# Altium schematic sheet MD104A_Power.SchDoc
size Letter; Date: Not shown in title block; ApprovedBy: Not shown in title block; CheckedBy: Not shown in title block; Author: Not shown in title block; CompanyName: Not shown in title block; Engineer: Not shown in title block; Organization: Not shown in title block; Address1: Not shown in title block; Address2: Not shown in title block; Address3: Not shown in title block; Address4: Not shown in title block; DocumentNumber: 4; Revision: Use project parameter SCH_Rev; SheetNumber: 4; SheetTotal: 5; PageSetup: Record=PageOptions¦CenterHorizontal=True¦CenterVertical=True¦PrintScale=1.00¦XCorrection=1.00¦YCorrection=1.00¦PrintKind=0¦BorderSize=5000000¦LeftOffset=0¦BottomOffset=0¦Orientation=2¦PaperLength=1000¦PaperWidth=1000¦Scale=100¦PaperSource=15¦PrintQuality=600¦MediaType=1¦DitherType=10¦PaperKind=Letter¦PrintScaleMode=1
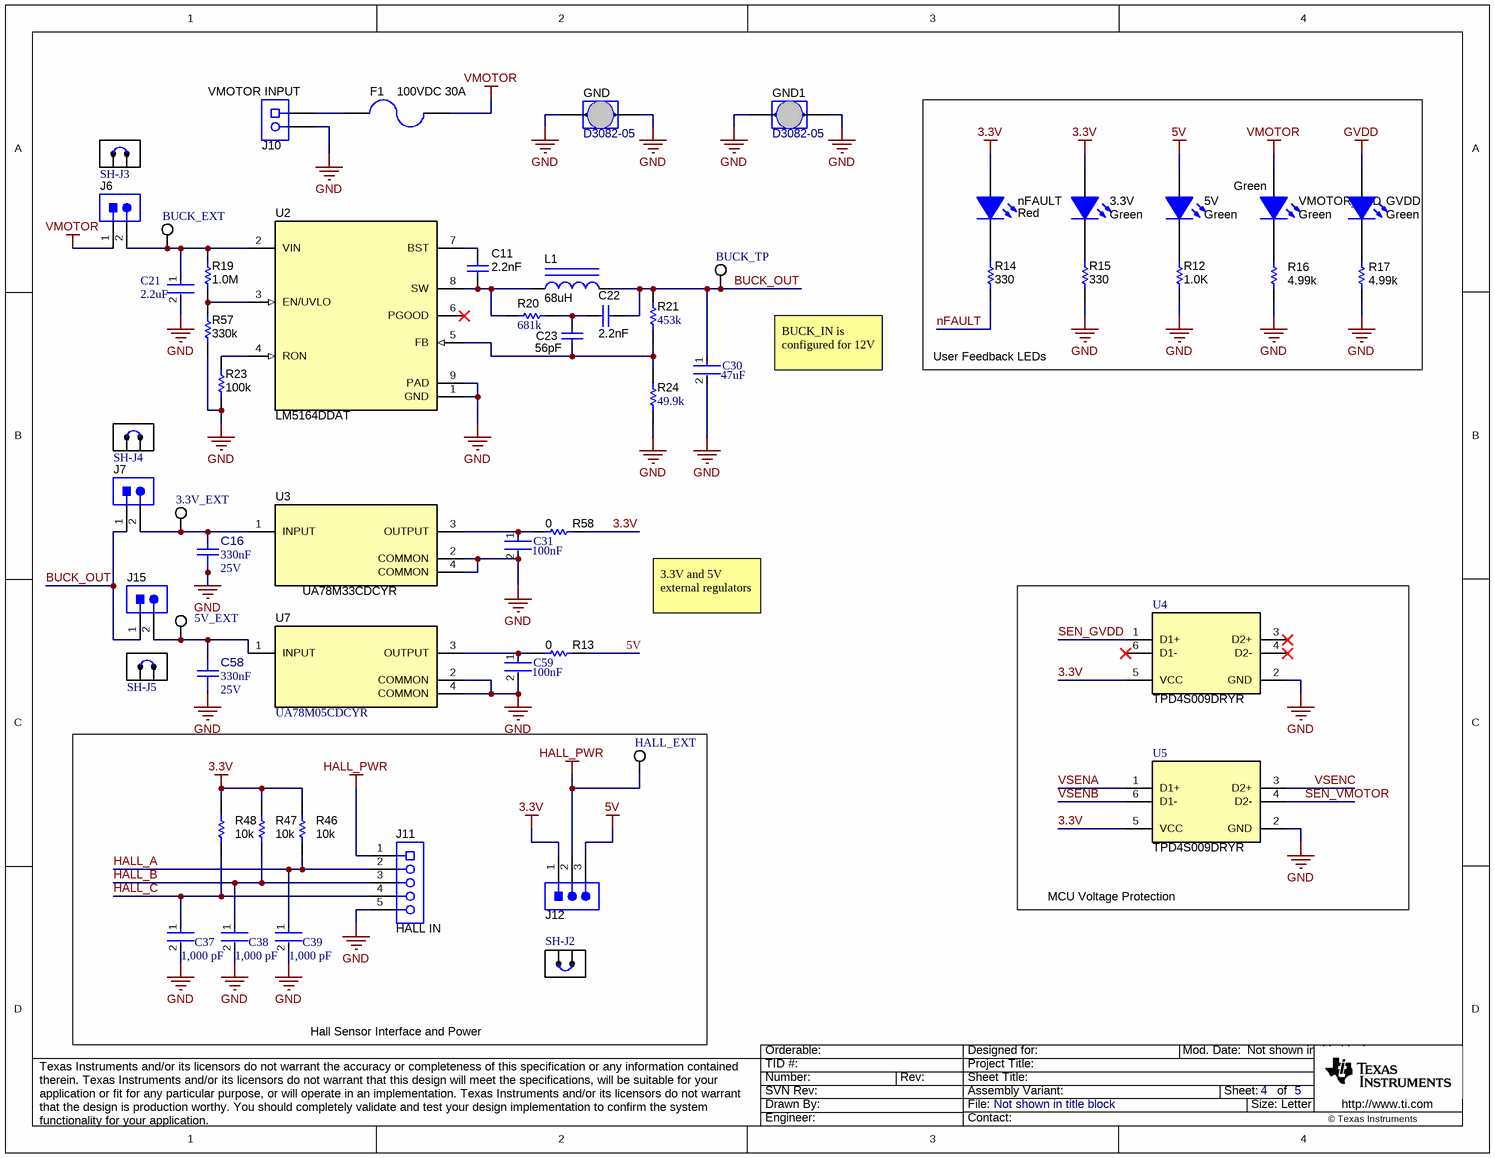
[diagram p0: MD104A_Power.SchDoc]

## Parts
3.3V  value Green  [LED_LTST-C171]
3.3V_EXT  5015  [Testpoint_Keystone_Miniature]  (value not drawn)
5V  5V: Green  [LED_LTST-C171]
5V_EXT  5015  [Testpoint_Keystone_Miniature]  (value not drawn)
BUCK_EXT  5015  [Testpoint_Keystone_Miniature]  (value not drawn)
BUCK_TP  5015  [Testpoint_Keystone_Miniature]  (value not drawn)
C11  Cap_F: 2.2nF  [0603L]  (hidden comment: CGA3E2X7R2A222K080AA)
C16  Cap_F: 330nF  VDC_V: 25V  [FP-CGA3E3X7R1E334K080AB_0603-MFG]  (hidden comment: CGA3E3X7R1E334K080AB)
C21  Capacitance: 2.2uF  [FP-C1210C225K1RACAUTO-MFG]  (hidden comment: C1210C225K1RACAUTO)
C22  Cap_F: 2.2nF  [0603L]  (hidden comment: CGA3E2X7R2A222K080AA)
C23  ValueDisplayed: 56pF  [0603L]  (hidden comment: C0603C560J1RACAUTO)
C30  Capacitance: 47uF  [FP-CGA9P-IPC_A]  (hidden comment: CGA9N3X7R1E476M230KB)
C31  Capacitance: 100nF  [FP-GCM155-0_05-IPC_A]  (hidden comment: GCM155R71C104KA55J)
C37  value 1,000 pF  [FP-C0603C-CF-MFG]  (hidden comment: C0603C102K4RACAUTO)
C38  value 1,000 pF  [FP-C0603C-CF-MFG]  (hidden comment: C0603C102K4RACAUTO)
C39  value 1,000 pF  [FP-C0603C-CF-MFG]  (hidden comment: C0603C102K4RACAUTO)
C58  Cap_F: 330nF  VDC_V: 25V  [FP-CGA3E3X7R1E334K080AB_0603-MFG]  (hidden comment: CGA3E3X7R1E334K080AB)
C59  Capacitance: 100nF  [FP-GCM155-0_05-IPC_A]  (hidden comment: GCM155R71C104KA55J)
F1  100VDC 30A  [Fuse_0463]
GND  D3082-05  [Harwin_D3082-05]
GND1  D3082-05  [Harwin_D3082-05]
GVDD  value Green  [LED_LTST-C171]
HALL_EXT  5015  [Testpoint_Keystone_Miniature]  (value not drawn)
J6  PBC02SAAN  [Sullins_PBC02SAAN]  (value not drawn)
J7  PBC02SAAN  [Sullins_PBC02SAAN]  (value not drawn)
J10  VMOTOR INPUT  [Phoenix_1902547]
J11  HALL IN  [Phoenix_1792892]
J12  61300311121  [WURTH_61300311121]  (value not drawn)
J15  PBC02SAAN  [Sullins_PBC02SAAN]  (value not drawn)
L1  ValueDisplayed: 68uH  [SDR1006]  (hidden comment: SDR1006-680KL)
nFAULT  value Red  [LED_LTST-C170_Red]
R12  ValueDisplayed: 1.0K  [0603L]  (hidden comment: CRCW0603330RJNEA)
R13  value 0  [0603L]  (hidden comment: CRCW06030000Z0EA)
R14  ValueDisplayed: 330  [0603L]  (hidden comment: CRCW0603330RJNEA)
R15  ValueDisplayed: 330  [0603L]  (hidden comment: CRCW0603330RJNEA)
R16  value 4.99k  [0603L]  (hidden comment: CRCW06034K99FKEA)
R17  value 4.99k  [0603L]  (hidden comment: CRCW06034K99FKEA)
R19  ValueDisplayed: 1.0M  [0603L]  (hidden comment: CRCW06031M00JNEA)
R20  ValueDisplayed: 681k  [0402]  (hidden comment: ERJ-2RKF4992X)
R21  ValueDisplayed: 453k  [0402]  (hidden comment: ERJ-2RKF4533X)
R23  ValueDisplayed: 100k  [0402L]  (hidden comment: CRCW0402100KFKED)
R24  ValueDisplayed: 49.9k  [0402]  (hidden comment: ERJ-2RKF4992X)
R46  value 10k  [0603L]  (hidden comment: CRCW060310K0JNEA)
R47  value 10k  [0603L]  (hidden comment: CRCW060310K0JNEA)
R48  value 10k  [0603L]  (hidden comment: CRCW060310K0JNEA)
R57  ValueDisplayed: 330k  [0603L]  (hidden comment: CRCW0603330KJNEA)
R58  value 0  [0603L]  (hidden comment: CRCW06030000Z0EA)
SH-J2  SNT-100-BK-G  [SNT-100-BK-G]  (value not drawn)
SH-J3  SNT-100-BK-G  [SNT-100-BK-G]  (value not drawn)
SH-J4  SNT-100-BK-G  [SNT-100-BK-G]  (value not drawn)
SH-J5  SNT-100-BK-G  [SNT-100-BK-G]  (value not drawn)
U2  LM5164DDAT  [DDA0008E_N]
U3  UA78M33CDCYR  [DCY0004A_N]
U4  TPD4S009DRYR  [DRY0006A]
U5  TPD4S009DRYR  [DRY0006A]
U7  UA78M05CDCYR  [DCY0004A_N]
VMOTOR_LED  Green  [LED_LTST-C171]

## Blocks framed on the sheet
User Feedback LEDs: 3.3V 5V GVDD nFAULT R12 R14-R17 VMOTOR_LED
MCU Voltage Protection: U4 U5
Hall Sensor Interface and Power: C37-C39 HALL_EXT J11 J12 R46-R48 SH-J2

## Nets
3.3V: 3.3V.1(A) J12.1 nFAULT.1(A) R46.1 R47.1 R48.1 R58.2 U4.5(VCC) U5.5(VCC)
5V: 5V.1(A) J12.3 R13.2
GND: C16.1 C21.2 C30.2 C31.2 C37.2 C38.2 C39.2 C58.1 C59.2 GND.1 GND.2 GND1.1 GND1.2 J10.2 J11.5 R12.1 R15.1 R16.1 R17.1 R23.1 R24.1 R57.1 U2.1(GND) U2.9(PAD) U3.2(COMMON) U3.4(COMMON) U4.2(GND) U5.2(GND) U7.2(COMMON) U7.4(COMMON)
GVDD: GVDD.1(A)
HALL_PWR: HALL_EXT.1 J11.1 J12.2
VMOTOR: F1.1 J6.1 VMOTOR_LED.1(A)
BUCK_OUT: BUCK_TP.1 C22.1 C30.1 J7.1 J15.1 L1.2 R21.2
HALL_A: C39.1 J11.2 R46.2
HALL_B: C38.1 J11.3 R47.2
HALL_C: C37.1 J11.4 R48.2
nFAULT: R14.1
SEN_GVDD: U4.1(D1+)
SEN_VMOTOR: U5.4(D2-)
VSENA: U5.1(D1+)
VSENB: U5.6(D1-)
VSENC: U5.3(D2+)
Net3.3V_2: 3.3V.2(K) R15.2
Net3.3V_EXT_1: 3.3V_EXT.1 C16.2 J7.2 U3.1(INPUT)
Net5V_2: 5V.2(K) R12.2
Net5V_EXT_1: 5V_EXT.1 C58.2 J15.2 U7.1(INPUT)
NetBUCK_EXT_1: BUCK_EXT.1 C21.1 J6.2 R19.2 U2.2(VIN)
NetC11_1: C11.1 U2.7(BST)
NetC11_2: C11.2 L1.1 R20.2 U2.8(SW)
NetC22_2: C22.2 C23.1 R20.1
NetC23_2: C23.2 R21.1 R24.2 U2.5(FB)
NetC31_1: C31.1 R58.1 U3.3(OUTPUT)
NetC59_1: C59.1 R13.1 U7.3(OUTPUT)
NetF1_2: F1.2 J10.1
NetGVDD_2: GVDD.2(K) R17.2
NetnFAULT_2: nFAULT.2(K) R14.2
NetR16_2: R16.2 VMOTOR_LED.2(K)
NetR19_1: R19.1 R57.2 U2.3(EN/UVLO)
NetR23_2: R23.2 U2.4(RON)

Not connected (* = marked no-connect by the designer): U2 6(PGOOD)*; U4 3(D2+)* 4(D2-)* 6(D1-)*

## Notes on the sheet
- BUCK_IN is configured for 12V
- 3.3V and 5V external regulators

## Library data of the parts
3.3V 5V GVDD VMOTOR_LED = CMP-0002830-3: LED, Green, SMD; Manufacturer: Lite-On; PartNumber: LTST-C171GKT; Vf_V: 2.1V; Io_A: 20A; Value1: W; SizeArea_mm2: 2.5; SizeAreaWB_mm2: 6.75; SizeX_mm: 2; SizeY_mm: 1.25; SizeZ_mm: 1.2
3.3V_EXT 5V_EXT BUCK_EXT BUCK_TP HALL_EXT = CMP-0055152-2: Test Point, Miniature, SMT; Manufacturer: Keystone Electronics; CT: TRUE; Green_Lifecycle: Active; Green_REACh: Passed; CNHeader: FALSE
C11 C22 = CMP-0007085-4: CAP, CERM, 2200 pF, 100 V, +/- 10%, X7R, AEC-Q200 Grade 1, 0603; Manufacturer: TDK; TaMin_C: -55°C; ESR_ohm: 0.923948; Polarized: N; SizeAreaWB_mm2: 4.68; Value1: 0.923948 ohm; U/M: EA; Value: 2200pF; TaMax_C: 125°C; SizeZ_mm: 1; SizeX_mm: 1.6; SizeY_mm: 0.8; Cap_Case: 0603; Value2: 100V; SizeArea_mm2: 1.28; AEC Qualified: Y; IRMS_A: 295.638mA; AEC Category: Q200
C16 C58 = CMP-0030960-1: Cap Ceramic 330nF 25V X7R 10% Pad SMD 0603 +125°C Automotive T/R; Manufacturer: TDK; AEC Grade: Grade 1; AEC Qualified: Yes; SizeZ_mm: 1.1mm; TempCo: 0.15; Tolerance_%: 0.1%
C21 = CMP-03020-034647-1: CAP CER 2.2UF 100V X7R 1210 AEC-Q200 C1210C225K1RACAUTO; Tolerance: 10%; Dielectric Material: Ceramic
C23 = CMP-0007275-4: CAP, CERM, 56 pF, 100 V, +/- 5%, 0603, AEC-Q200; Manufacturer: MuRata; PartNumber: GRM1885C2A560JA01D; TaMin_C: -55°C; Polarized: N; TempCo: C0G/NP0; SizeAreaWB_mm2: 4.68; Value1: Unknown; U/M: EA; Value: 56pF; TaMax_C: 125°C; SizeZ_mm: 1; SizeX_mm: 1.6; SizeY_mm: 0.8; Cap_Case: 0603; Value2: 100V; SizeArea_mm2: 1.28; AEC Category: Q200
C30 = CMP-08246-000867-1: Cap Ceramic 47uF 25V X7R 20% Pad SMD 2220 +125°C Automotive T/R CGA9N3X7R1E476M230KB
C31 C59 = CMP-2008-03712-2: Ceramic Capacitor for Automotive 100nF ±10% 16VDC X7R 0402 Paper T/R GCM155R71C104KA55J; Voltage Rating: 16V
C37-C39 = CMP-03020-019178-1: CAP CER SMD 0603 1000PF 10% X7R C0603C102K4RACAUTO; Manufacturer: KEMET; Temperature Coefficient: 30ppm/°C; Voltage Rating: 16 V; Material: Ceramic; Tolerance: 0.1; Automotive Grade: Grade 1
F1 = CMP-0077200-3: Fuse, 30 A, 250 VAC, 100 VDC, SMD; PartNumber: 0463030.ER; Manufacturer: Littelfuse; VAC_V: 250V; SizeAreaWB_mm2: 61.952; Rtyp_Ohm: 1.93m; SizeArea_mm2: 31.512; MeltingTyp: 916; SizeZ_mm: 3.12; VDC_V: 100V; SizeX_mm: 10.1; Interrupt_AC: 100A; Interrupt_DC: 50A; Fuse Speed: Fast; Fuse Technology: Board Mount; TaMax_C: 125°C; TaMin_C: -55°C
GND GND1 = CMP-0075110-1: 1mm Uninsulated Shorting Plug, 10.16mm spacing, TH; Manufacturer: Harwin; CNHeader: False; Green_Lifecycle: Active; Green_REACh: Passed; CompType: Jumper Wire
J6 J7 J15 = CMP-0054566-1: Header, 100mil, 2x1, Gold, TH; Manufacturer: Sullins Connector Solutions; CNHeader: TRUE; Current_A: 3A; Green_Lifecycle: Active; Shrouded: N; Gender: Male; Green_REACh: Passed; Voltage_V: 1.8kV; Row_Count: 1; Pitch_mm: 2.54; CT: FALSE; Cert_UL: Y
J10 = CMP-0055527-1: Terminal Block, 9.52mm, 2x1, R/A, TH; PartNumber: 1902547; Manufacturer: Phoenix Contact; Pitch_mm: 9.52; Gender: Female; Row_Count: 1; Current_A: 32A; Voltage_V: 1kV; Cert_UL: Y; CNHeader: FALSE; CT: TRUE
J11 = CMP-0055532-1: Terminal Block, 5mm, 5x1, R/A, TH; Manufacturer: Phoenix Contact; PartNumber: 1792892; Cert_VDE: Y; CNHeader: FALSE; Current_A: 16A; Gender: Female; Voltage_V: 400V; Row_Count: 1; Pitch_mm: 5; CT: TRUE
J12 = CMP-0054796-4: Header, 2.54 mm, 3x1, Gold, TH; Manufacturer: Wurth Elektronik; Green_Lifecycle: Active; Green_REACh: Passed; CNHeader: TRUE; CT: FALSE
L1 = CMP-0057541-2: Inductor, Drum Core, Ferrite, 68 uH, 1.1 A, 0.22 ohm, SMD; Manufacturer: Bourns; Isat: 2A @ 10% inductance drop; Irms: 1.1A @ 40C rise; Green_Lifecycle: Active; SizeAreaWB_mm2: 139.24; DCR_ohm: 0.22; Green_REACh: Passed; Value: 68uH; Imax_A: 1.1A; SizeZ_mm: 5.8; SizeX_mm: 9.8; SizeArea_mm2: 96.04; Ind_H: 68µH; AEC Category: Q200
nFAULT = CMP-0002829-3: LED, Red, SMD; Manufacturer: Lite-On; PartNumber: LTST-C170KRKT; Io_A: 20mA; SizeAreaWB_mm2: 6.75; Value1: W; SizeZ_mm: 1.2; SizeX_mm: 2; SizeY_mm: 1.25; Vf_V: 2V; SizeArea_mm2: 2.5
R12 R14 R15 = CMP-0025785-4: RES, 330, 5%, 0.1 W, AEC-Q200 Grade 0, 0603; Manufacturer: Vishay-Dale; Power_W: 100mW; TempCo: 200 ppm/C; Value_Code: 330R; Value: 330; EIA_Code: E24; SizeX_mm: 1.6; SizeY_mm: 0.8; SizeZ_mm: 1; Value2: 0.1W; SizeArea_mm2: 1.28; CompType: Resistor; AEC Qualified: Y; VDC_V: 75V; AEC Category: Q200; AEC Grade: 0
R13 R58 = CMP-0025697-4: RES, 0, 5%, 0.1 W, AEC-Q200 Grade 0, 0603; Manufacturer: Vishay-Dale; Value_Code: 0000; Power_W: 100mW; Value2: 0.1W; VDC_V: 75V; TempCo: 200 ppm/C; EIA_Code: E24; AEC Category: Q200; AEC Qualified: Y; SizeArea_mm2: 1.28; SizeX_mm: 1.6; SizeY_mm: 0.8; SizeZ_mm: 1
R16 R17 = CMP-0022458-4: RES, 4.99 k, 1%, 0.1 W, AEC-Q200 Grade 0, 0603; Manufacturer: Vishay-Dale; Value_Code: 4k99; Power_W: 100mW; Value2: 0.1W; VDC_V: 75V; TempCo: 100 ppm/C; EIA_Code: E96; AEC Category: Q200; AEC Qualified: Y; AEC Grade: 0; SizeArea_mm2: 1.28; SizeX_mm: 1.6; SizeY_mm: 0.8; SizeZ_mm: 1
R19 = CMP-0025736-4: RES, 1.0 M, 5%, 0.1 W, AEC-Q200 Grade 0, 0603; Manufacturer: Vishay-Dale; Power_W: 100mW; TempCo: 200 ppm/C; Value_Code: 1M00; Value: 1.0Meg; EIA_Code: E24; Res_ohm: 1M; SizeX_mm: 1.6; SizeY_mm: 0.8; SizeZ_mm: 1; Value2: 0.1W; SizeArea_mm2: 1.28; AEC Qualified: Y; VDC_V: 75V; AEC Category: Q200; AEC Grade: 0
R20 = CMP-0026702-1: RES, 681k, 1%, 0.1 W, AEC-Q200 Grade 0, 0402; Manufacturer: Panasonic; PartNumber: ERJ-2RKF6813X; Power_W: 100mW; TempCo: 100 ppm/C; U/M: EA; EIA_Code: E96; SizeX_mm: 1; SizeY_mm: 0.5; SizeZ_mm: 0.6; Value2: 0.1W; AEC Qualified: Y; VDC_V: 50V; AEC Grade: 0; AEC Category: Q200
R21 = CMP-0026702-1: RES, 453 k 1%, 0.1 W, AEC-Q200 Grade 0, 0402; Manufacturer: Panasonic; Power_W: 100mW; TempCo: 100 ppm/C; U/M: EA; Value: 453k; EIA_Code: E96; SizeX_mm: 1; SizeY_mm: 0.5; SizeZ_mm: 0.6; Value2: 0.1W; AEC Qualified: Y; VDC_V: 50V; AEC Grade: 0; AEC Category: Q200
R23 = CMP-0025950-3: RES, 100 k, 1%, 0.063 W, AEC-Q200 Grade 0, 0402; Manufacturer: Vishay-Dale; Power_W: 63mW; TempCo: 100 ppm/C; Value: 100k; EIA_Code: E96; SizeX_mm: 1; SizeY_mm: 0.5; SizeZ_mm: 0.6; Value2: 0.063W; AEC Qualified: Y; VDC_V: 50V; AEC Category: Q200; AEC Grade: 0
R24 = CMP-0026702-1: RES, 49.9 k, 1%, 0.1 W, AEC-Q200 Grade 0, 0402; Manufacturer: Panasonic; Power_W: 100mW; TempCo: 100 ppm/C; Value_Code: 49k9; U/M: EA; Value: 49.9k; EIA_Code: E96; SizeX_mm: 1; SizeY_mm: 0.5; SizeZ_mm: 0.6; Value2: 0.1W; AEC Qualified: Y; VDC_V: 50V; AEC Grade: 0; AEC Category: Q200
R46-R48 = CMP-0025701-4: RES, 10 k, 5%, 0.1 W, AEC-Q200 Grade 0, 0603; Manufacturer: Vishay-Dale; Value_Code: 10k0; Power_W: 100mW; Value2: 0.1W; VDC_V: 75V; TempCo: 200 ppm/C; EIA_Code: E24; AEC Category: Q200; AEC Qualified: Y; AEC Grade: 0; SizeArea_mm2: 1.28; SizeX_mm: 1.6; SizeY_mm: 0.8; SizeZ_mm: 1
R57 = CMP-0025784-4: RES, 330 k, 5%, 0.1 W, AEC-Q200 Grade 0, 0603; Manufacturer: Vishay-Dale; Power_W: 100mW; TempCo: 200 ppm/C; Value: 330k; EIA_Code: E24; SizeX_mm: 1.6; SizeY_mm: 0.8; SizeZ_mm: 1; Value2: 0.1W; SizeArea_mm2: 1.28; AEC Qualified: Y; VDC_V: 75V; AEC Category: Q200; AEC Grade: 0
SH-J2-SH-J5 = CMP-0003623-3: Shunt, 100mil, Gold plated, Black; Alternate PartNumber: 969102-0000-DA; Manufacturer: Samtec; Alternate Manufacturer: 3M; Value: 1x2
U2 = CMP-0080798-1: 100-V Low IQ Synchronous Buck Regulator, DDA0008E (SOIC-8); Alternate Manufacturer: Texas Instruments; SizeAreaWB_mm2: 57.4; SizeZ_mm: 1.7; SizeX_mm: 5; SizeY_mm: 6.2; SizeArea_mm2: 31; CompType: IC; AEC Qualified: N; AEC Category: Q200
U3 = CMP-0080825-1: 500-mA, 25-V, Linear Voltage Regulators, DCY0004A (SOT-223-4); Alternate Manufacturer: Texas Instruments; Green_Lifecycle: Active; SizeAreaWB_mm2: 76.5; Green_REACh: Passed; SizeZ_mm: 1.8; SizeX_mm: 7; SizeY_mm: 6.5; SizeArea_mm2: 45.5; CompType: IC; AEC Qualified: N; AEC Category: Q200
U4 U5 = CMP-0043120-3: 4-Channel ESD Solution for High-Speed Differential Interface, DRY0006A (USON-6); Manufacturer: Texas Instruments; Eco-Plan: Green (RoHS & no Sb/Br); Differential Capacitance(pF): 0.05; IEC 61000-4-2 Contact(+/- kV): 8; IO Capacitance(Typ)(pF): 0.8; Breakdown Voltage(Min)(V): 9; IO Leakage Current(nA): Jan-00; AEC Category: Q200; AEC Qualified: N; CompType: IC; SizeAreaWB_mm2: 4.9; SizeArea_mm2: 1.45; SizeX_mm: 1.0; SizeZ_mm: 0.6; Rating: Catalog
U7 = CMP-0080822-1: 500-mA, 25-V, Linear Voltage Regulators, DCY0004A (SOT-223-4); Alternate Manufacturer: Texas Instruments; SizeAreaWB_mm2: 76.5; SizeZ_mm: 1.8; SizeX_mm: 7; SizeY_mm: 6.5; SizeArea_mm2: 45.5; CompType: IC; AEC Qualified: N; AEC Category: Q200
